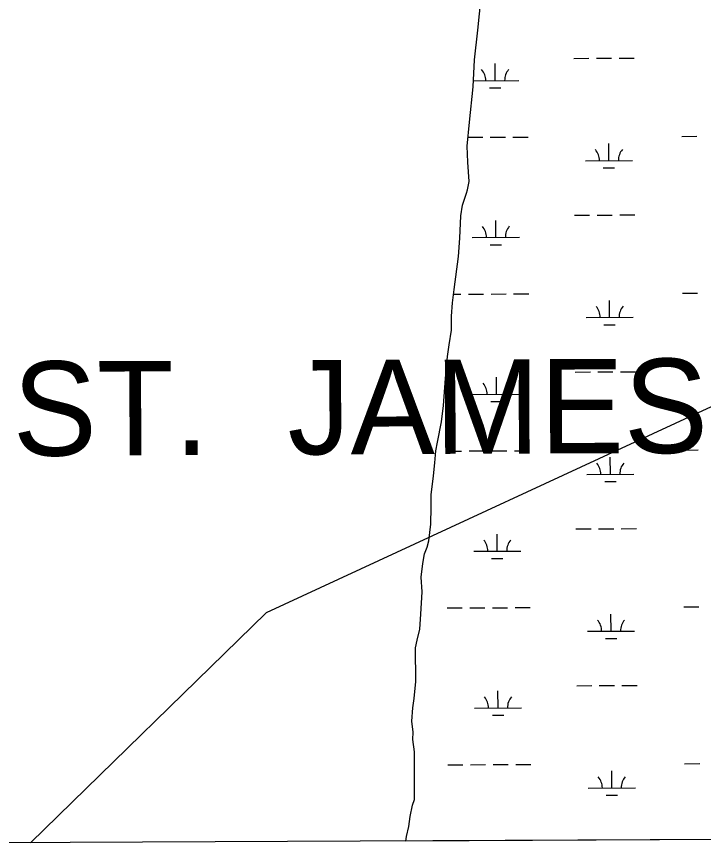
# Model space of a CAD drawing. Extents: x 3424494 to 3462436, y 522220 to 547718.
# Drawn here: x 3439589 to 3441045, y 527644 to 529412 of the extents above; entities that cross this region are included whole.
import ezdxf

# ---------------------------------------------------------------- set-up
doc = ezdxf.new("R2010")
doc.units = 0
for name, color, linetype in [('V-SITE-VEGE', 7, 'Continuous'), ('V-TOPO-GNAM-IDEN', 7, 'Continuous'), ('V-TOPO-SHOR', 7, 'Continuous'), ('V-WETL-SWMP', 7, 'Continuous')]:
    doc.layers.add(name, color=color, linetype=linetype)

msp = doc.modelspace()

# ---------------------------------------------------------------- linework, layer by layer
at = {"layer": 'V-SITE-VEGE'}
msp.add_line((3441266, 527667.3), (3436031.7, 527643.7), dxfattribs=at)
at = {"layer": 'V-TOPO-SHOR'}
msp.add_lwpolyline([(3442245.8, 528756.3), (3441572.1, 528672.8), (3441137.4, 528619.6), (3440117.5, 528147.6), (3439618.1, 527659.9)], dxfattribs=at)
at = {"layer": 'V-WETL-SWMP'}
for p, q in [((3440566.8, 529383.5), (3440580.2, 529519.9)), ((3440559.4, 529320.2), (3440566.8, 529383.5)), ((3440556.3, 529263.1), (3440559.4, 529320.2)), ((3440770.1, 529323.6), (3440802.1, 529323.7)), ((3440818.1, 529323.8), (3440850.1, 529324)), ((3440866.1, 529324), (3440898.1, 529324.2)), ((3440603.2, 529276.4), (3440603.1, 529312.4)), ((3440548.8, 529188), (3440556.3, 529263.1)), ((3440557, 529276.2), (3440653.2, 529276.6)), ((3440591.3, 529260.9), (3440615.3, 529261)), ((3440543.6, 529137.2), (3440548.8, 529188)), ((3440545.6, 529156.1), (3440576.9, 529156.2)), ((3440592.9, 529156.3), (3440624.9, 529156.4)), ((3440640.9, 529156.5), (3440672.9, 529156.7)), ((3440998.8, 529158.1), (3441030.8, 529158.3)), ((3440545.5, 529103.1), (3440543.6, 529137.2)), ((3440844.5, 529106.7), (3440844.3, 529142.7)), ((3440548, 529062.7), (3440545.5, 529103.1)), ((3440794.5, 529106.5), (3440894.5, 529106.9)), ((3440832.5, 529091.2), (3440856.5, 529091.3)), ((3440544.4, 529044.6), (3440548, 529062.7)), ((3440533.8, 529011.9), (3440542.3, 529037.6)), ((3440542.3, 529037.6), (3440544.4, 529044.6)), ((3440530.2, 528989.7), (3440533.8, 529011.9)), ((3440528.5, 528942.3), (3440530.2, 528989.7)), ((3440604.7, 528943.8), (3440604.6, 528979.8)), ((3440771.6, 528990.9), (3440803.6, 528991.1)), ((3440819.6, 528991.1), (3440851.6, 528991.3)), ((3440867.6, 528991.4), (3440899.6, 528991.5)), ((3440525.4, 528903.4), (3440528.5, 528942.3)), ((3440554.7, 528943.5), (3440654.7, 528944)), ((3440592.8, 528928.3), (3440616.8, 528928.4)), ((3440516.6, 528833.1), (3440525.4, 528903.4)), ((3440513, 528805.3), (3440516.6, 528833.1)), ((3440515.3, 528823.3), (3440530.4, 528823.3)), ((3440546.4, 528823.4), (3440578.4, 528823.6)), ((3440594.4, 528823.6), (3440626.4, 528823.8)), ((3440642.4, 528823.9), (3440674.4, 528824)), ((3441000.3, 528825.5), (3441032.3, 528825.6)), ((3440510.7, 528776.8), (3440513, 528805.3)), ((3440846, 528774), (3440845.8, 528810)), ((3440510.5, 528746.8), (3440510.7, 528776.8)), ((3440796, 528773.8), (3440896, 528774.3)), ((3440834, 528758.5), (3440858, 528758.7)), ((3440505.4, 528716.2), (3440510.5, 528746.8)), ((3440501.8, 528691.2), (3440505.4, 528716.2)), ((3440500.3, 528669.6), (3440501.8, 528691.2)), ((3440498, 528644.6), (3440500.3, 528669.6)), ((3440493.5, 528587.5), (3440498, 528644.6)), ((3440606.2, 528611.1), (3440606.1, 528647.1)), ((3440773.1, 528658.3), (3440805.1, 528658.4)), ((3440821.1, 528658.5), (3440853.1, 528658.6)), ((3440869.1, 528658.7), (3440901.1, 528658.8)), ((3440556.2, 528610.9), (3440656.2, 528611.3)), ((3440594.3, 528595.6), (3440618.3, 528595.7)), ((3440489.1, 528552.7), (3440493.5, 528587.5)), ((3440481.1, 528509.6), (3440489.1, 528552.7)), ((3440477.5, 528490.8), (3440481.1, 528509.6)), ((3440475.3, 528465.8), (3440477.5, 528490.8)), ((3440499.9, 528490.5), (3440531.9, 528490.7)), ((3440547.9, 528490.8), (3440579.9, 528490.9)), ((3440595.9, 528491), (3440627.9, 528491.1)), ((3440643.9, 528491.2), (3440675.9, 528491.3)), ((3441001.8, 528492.8), (3441033.8, 528492.9)), ((3440472.3, 528438), (3440475.3, 528465.8)), ((3440847.5, 528441.4), (3440847.3, 528477.4)), ((3440467.2, 528397.6), (3440472.3, 528438)), ((3440797.5, 528441.1), (3440897.5, 528441.6)), ((3440835.6, 528425.9), (3440859.6, 528426)), ((3440467.7, 528371.9), (3440467.2, 528397.6)), ((3440466.8, 528335.7), (3440467.7, 528371.9)), ((3440462.4, 528300.2), (3440466.8, 528335.7)), ((3440774.6, 528325.6), (3440806.6, 528325.7)), ((3440822.6, 528325.8), (3440854.6, 528326)), ((3440870.6, 528326), (3440902.6, 528326.2)), ((3440607.8, 528278.4), (3440607.6, 528314.4)), ((3440458.8, 528287), (3440462.4, 528300.2)), ((3440449.6, 528252.2), (3440453.2, 528272.4)), ((3440453.2, 528272.4), (3440458.8, 528287)), ((3440557.8, 528278.2), (3440657.8, 528278.6)), ((3440595.8, 528262.9), (3440619.8, 528263)), ((3440446.6, 528223), (3440449.6, 528252.2)), ((3440448.5, 528191.7), (3440446.6, 528223)), ((3440445.4, 528145), (3440448.5, 528191.7)), ((3440501.5, 528157.9), (3440533.5, 528158)), ((3440549.5, 528158.1), (3440581.5, 528158.2)), ((3440597.5, 528158.3), (3440629.5, 528158.4)), ((3440645.5, 528158.5), (3440677.5, 528158.7)), ((3441003.4, 528160.1), (3441035.4, 528160.3)), ((3440443.8, 528113), (3440445.4, 528145)), ((3440849, 528108.7), (3440848.8, 528144.7)), ((3440438.1, 528089.4), (3440443.8, 528113)), ((3440799, 528108.5), (3440899, 528108.9)), ((3440434.5, 528073.4), (3440438.1, 528089.4)), ((3440837.1, 528093.2), (3440861.1, 528093.3)), ((3440434.7, 528001.7), (3440434.5, 528073.4)), ((3440431.7, 527965.5), (3440434.7, 528001.7)), ((3440776.1, 527992.9), (3440808.1, 527993.1)), ((3440824.1, 527993.2), (3440856.1, 527993.3)), ((3440872.1, 527993.4), (3440904.1, 527993.5)), ((3440609.3, 527945.8), (3440609.1, 527981.8)), ((3440428.8, 527946), (3440431.7, 527965.5)), ((3440426.5, 527917.5), (3440428.8, 527946)), ((3440559.3, 527945.5), (3440659.3, 527946)), ((3440429.2, 527894.5), (3440426.5, 527917.5)), ((3440597.3, 527930.3), (3440621.3, 527930.4)), ((3440428.8, 527878.5), (3440429.2, 527894.5)), ((3440432.1, 527852.6), (3440428.8, 527878.5)), ((3440432.1, 527825.7), (3440432.1, 527852.6)), ((3440432.2, 527775.1), (3440432.1, 527825.7)), ((3440503, 527825.2), (3440535, 527825.4)), ((3440551, 527825.4), (3440583, 527825.6)), ((3440599, 527825.6), (3440631, 527825.8)), ((3440647, 527825.9), (3440679, 527826)), ((3440850.5, 527776), (3440850.3, 527812)), ((3441004.9, 527827.5), (3441036.9, 527827.6)), ((3440800.5, 527775.8), (3440900.5, 527776.3)), ((3440432.2, 527751.5), (3440432.2, 527775.1)), ((3440838.6, 527760.5), (3440862.6, 527760.7)), ((3440427.7, 527739.2), (3440432.2, 527751.5)), ((3440423.2, 527715.6), (3440427.7, 527739.2)), ((3440419.8, 527694.2), (3440423.2, 527715.6)), ((3440415.3, 527672.9), (3440419.8, 527694.2)), ((3440413.7, 527663.5), (3440415.3, 527672.9)), ((3441263.2, 527667.3), (3440413.7, 527663.5))]:
    msp.add_line(p, q, dxfattribs=at)
for centre, start, end in [((3440548, 529276.6), 359.4865, 41.0302), ((3440658.5, 529277.1), 139.4865, 181.0302), ((3440789.2, 529106.9), 359.4865, 41.0302), ((3440899.7, 529107.4), 139.4865, 181.0302), ((3440549.5, 528944), 359.4865, 41.0302), ((3440660, 528944.5), 139.4865, 181.0302), ((3440790.7, 528774.3), 359.4865, 41.0302), ((3440901.2, 528774.8), 139.4865, 181.0302), ((3440551, 528611.3), 359.4865, 41.0302), ((3440661.5, 528611.8), 139.4865, 181.0302), ((3440902.7, 528442.1), 139.4865, 181.0302), ((3440792.2, 528441.6), 359.4865, 41.0302), ((3440552.5, 528278.6), 359.4865, 41.0302), ((3440663, 528279.1), 139.4865, 181.0302), ((3440793.8, 528108.9), 359.4865, 41.0302), ((3440904.2, 528109.4), 139.4865, 181.0302), ((3440554, 527946), 359.4865, 41.0302), ((3440664.5, 527946.5), 139.4865, 181.0302), ((3440795.3, 527776.3), 359.4865, 41.0302), ((3440905.7, 527776.8), 139.4865, 181.0302)]:
    msp.add_arc(centre, 35.2, start, end, dxfattribs=at)

# ---------------------------------------------------------------- texts
at = {"layer": 'V-TOPO-GNAM-IDEN'}
for s, p in [('ST.', (3439580.5, 528480.6)), ('JAMES', (3440163.2, 528483.4))]:
    msp.add_text(s, height=200, rotation=0.2224, dxfattribs=at).set_placement(p)

doc.saveas('drawing.dxf')
